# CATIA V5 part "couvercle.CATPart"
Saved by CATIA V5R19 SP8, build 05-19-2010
Part number: couvercle
Revision: ANY
Definition: UNKNOWN
Nomenclature: couvercle
Source: Unknown
Bounding box of the stored display mesh (mm): x 0 to 163, y 0 to 77, z -1 to 7.5
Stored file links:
  D:\Documents\1_Travail\1 - ac-limoges.fr\ac-limoges.fr\Emmanuel Maynard - STI2D_Turgot\2 -2I2D\2_SEQUENCE_Serrure_Biométrique\5-Spé_ITEC\Serrure_Bio_Eleve\couvercle.CATPart
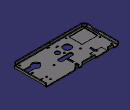
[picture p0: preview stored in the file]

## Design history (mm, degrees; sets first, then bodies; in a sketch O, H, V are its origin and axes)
Body1 "Enlèv. mat.-Extru.26" (main body)
  Solid1: solid without history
